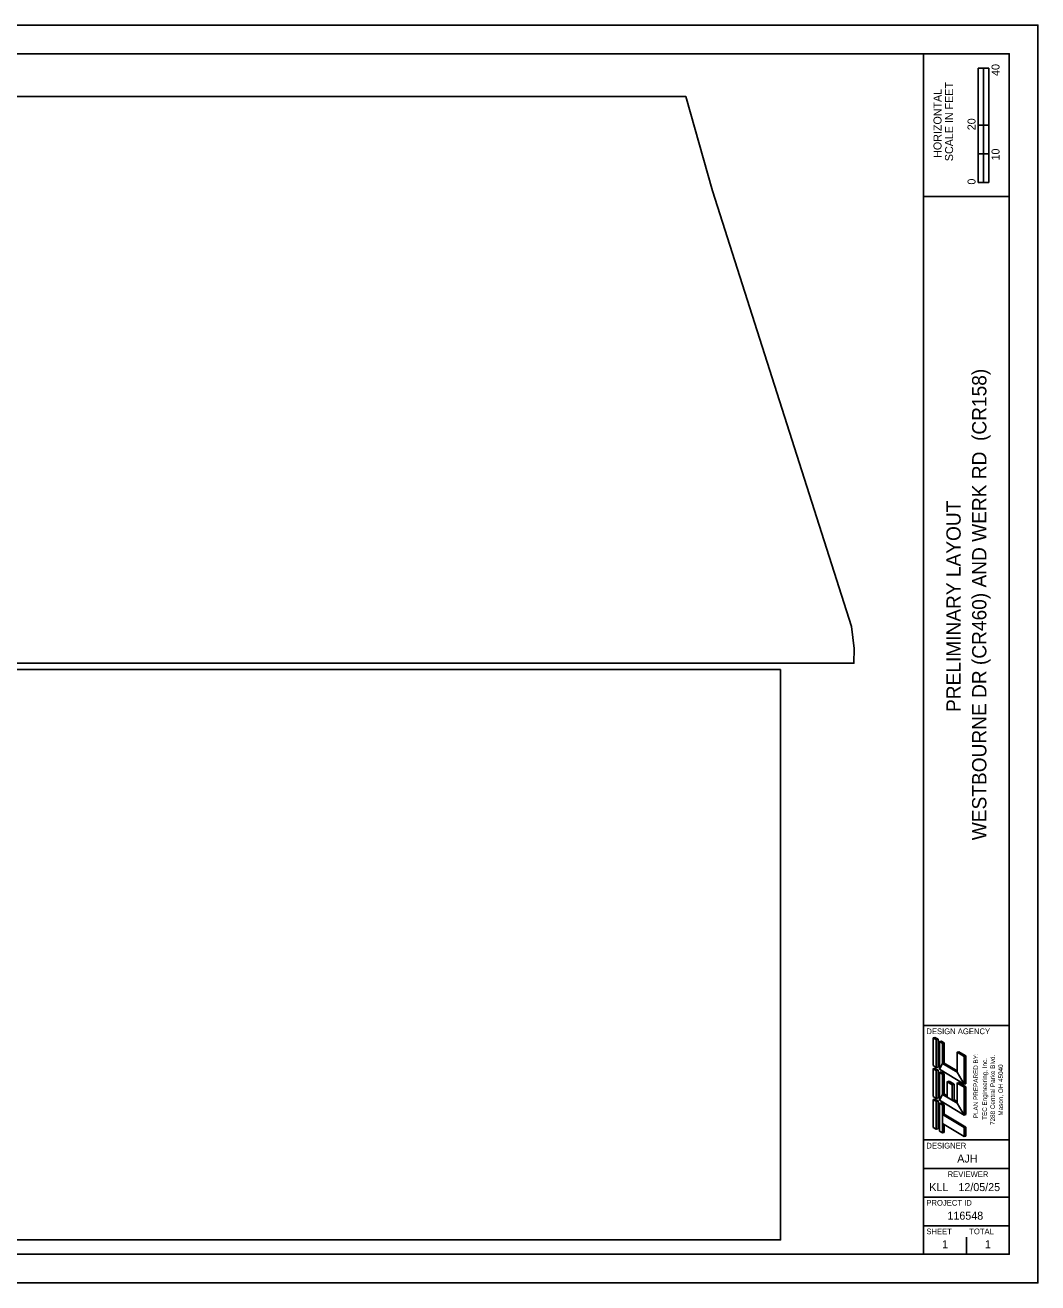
# Model space of a CAD drawing. Extents: x -1.4 to 34, y 0 to 22.
# Drawn here: x 16.29 to 34, y 0 to 22 of the extents above; entities that cross this region are included whole.
import ezdxf

# ---------------------------------------------------------------- set-up
doc = ezdxf.new("R2010")
doc.units = 0
for name, color, linetype in [('Default', 7, 'Continuous'), ('SC_Scratch1', 7, 'Continuous'), ('SH_Border', 7, 'Continuous'), ('SH_Cut_Line', 7, 'Continuous'), ('SH_Data', 7, 'Continuous'), ('SH_Text', 7, 'Continuous')]:
    doc.layers.add(name, color=color, linetype=linetype)

msp = doc.modelspace()

# ---------------------------------------------------------------- linework, layer by layer
at = {"layer": 'SC_Scratch1'}
for points in [[(27.845, 20.75), (4.5, 20.75), (4.5, 10.838), (30.783, 10.838), (30.786, 11.094), (30.743, 11.482), (28.307, 19.103)], [(27.845, 20.75), (7.965, 20.75), (7.965, 20.005), (4.5, 20.004), (4.5, 10.838), (30.783, 10.838), (30.786, 11.094), (30.743, 11.482), (28.307, 19.103)], [(29.5, 10.727), (4.5, 10.727), (4.5, 0.75), (29.5, 0.75)], [(29.5, 10.727), (4.5, 10.727), (4.5, 0.75), (29.5, 0.75)]]:
    msp.add_lwpolyline(points, close=True, dxfattribs=at)
at = {"layer": 'SH_Border'}
for p, q in [((32, 0.5), (32, 21.5)), ((32, 19), (33.5, 19)), ((32, 4.5), (33.5, 4.5)), ((32, 2.5), (33.5, 2.5)), ((32, 2), (33.5, 2)), ((32, 1.5), (33.5, 1.5)), ((32, 1), (33.5, 1))]:
    msp.add_line(p, q, dxfattribs=at)
msp.add_lwpolyline([(1.5, 21.5), (33.5, 21.5), (33.5, 0.5), (1.5, 0.5)], close=True, dxfattribs=at)
at = {"layer": 'SH_Cut_Line'}
msp.add_lwpolyline([(0, 0), (34, 0), (34, 22), (0, 22)], close=True, dxfattribs=at)
at = {"layer": 'SH_Data'}
for p, q in [((32.957, 19.25), (32.957, 21.25)), ((33.144, 21.25), (32.957, 21.25)), ((32.957, 20.25), (32.957, 21.25)), ((32.957, 21.25), (33.05, 21.25)), ((33.05, 21.25), (33.051, 21.25)), ((33.051, 21.25), (33.051, 20.25)), ((33.144, 21.25), (33.144, 19.25)), ((33.051, 20.25), (32.957, 20.25)), ((33.143, 20.25), (33.05, 20.25)), ((33.05, 20.25), (33.05, 19.75)), ((33.143, 19.75), (33.143, 20.25)), ((33.05, 19.75), (32.957, 19.75)), ((32.957, 19.75), (32.957, 19.25)), ((33.05, 19.25), (33.05, 19.75)), ((33.05, 19.75), (33.143, 19.75)), ((33.144, 19.25), (32.957, 19.25)), ((32.957, 19.25), (33.05, 19.25)), ((32.75, 3.5), (32.75, 3.5)), ((32.375, 0.675), (32.375, 0.675)), ((32.75, 0.5), (32.75, 0.8))]:
    msp.add_line(p, q, dxfattribs=at)
at = {"layer": 'SH_Text'}
for p, q in [((32.169, 4.285), (32.201, 4.294)), ((32.169, 3.799), (32.169, 4.285)), ((32.223, 4.253), (32.169, 4.285)), ((32.255, 4.261), (32.201, 4.294)), ((32.223, 4.253), (32.255, 4.261)), ((32.223, 3.767), (32.223, 4.253)), ((32.255, 3.775), (32.255, 4.261)), ((32.277, 4.221), (32.309, 4.229)), ((32.331, 4.188), (32.277, 4.221)), ((32.277, 3.735), (32.277, 4.221)), ((32.309, 4.229), (32.363, 4.196)), ((32.331, 4.188), (32.363, 4.196)), ((32.331, 3.837), (32.331, 4.188)), ((32.363, 4.196), (32.363, 3.845)), ((32.587, 4.034), (32.62, 4.042)), ((32.587, 3.683), (32.587, 4.034)), ((32.709, 3.961), (32.587, 4.034)), ((32.62, 4.042), (32.741, 3.97)), ((32.709, 3.961), (32.741, 3.97)), ((32.709, 3.475), (32.709, 3.961)), ((32.741, 3.97), (32.741, 3.484)), ((32.223, 3.767), (32.169, 3.799)), ((32.169, 3.745), (32.201, 3.754)), ((32.169, 3.259), (32.169, 3.745)), ((32.223, 3.713), (32.169, 3.745)), ((32.255, 3.722), (32.201, 3.754)), ((32.223, 3.767), (32.255, 3.775)), ((32.331, 3.837), (32.363, 3.845)), ((32.587, 3.683), (32.331, 3.837)), ((32.363, 3.845), (32.587, 3.711)), ((32.223, 3.713), (32.255, 3.722)), ((32.223, 3.227), (32.223, 3.713)), ((32.255, 3.236), (32.255, 3.722)), ((32.709, 3.475), (32.277, 3.735)), ((32.277, 3.681), (32.309, 3.689)), ((32.277, 3.195), (32.277, 3.681)), ((32.331, 3.648), (32.277, 3.681)), ((32.309, 3.689), (32.363, 3.656)), ((32.331, 3.648), (32.363, 3.656)), ((32.331, 3.297), (32.331, 3.648)), ((32.363, 3.656), (32.363, 3.305)), ((32.415, 3.519), (32.448, 3.527)), ((32.448, 3.527), (32.535, 3.474)), ((32.331, 3.297), (32.363, 3.305)), ((32.363, 3.305), (32.415, 3.274)), ((32.415, 3.519), (32.415, 3.247)), ((32.415, 3.519), (32.503, 3.466)), ((32.503, 3.466), (32.535, 3.474)), ((32.503, 3.466), (32.503, 3.194)), ((32.535, 3.474), (32.535, 3.202)), ((32.587, 3.494), (32.62, 3.502)), ((32.587, 3.143), (32.587, 3.494)), ((32.709, 3.421), (32.587, 3.494)), ((32.62, 3.502), (32.741, 3.43)), ((32.709, 3.475), (32.741, 3.484)), ((32.709, 3.421), (32.741, 3.43)), ((32.709, 2.935), (32.709, 3.421)), ((32.741, 3.43), (32.741, 2.944)), ((32.223, 3.227), (32.169, 3.259)), ((32.169, 3.205), (32.201, 3.215)), ((32.169, 2.719), (32.169, 3.205)), ((32.223, 3.173), (32.169, 3.205)), ((32.255, 3.181), (32.201, 3.215)), ((32.222, 3.173), (32.255, 3.181)), ((32.223, 3.227), (32.255, 3.236)), ((32.223, 2.687), (32.223, 3.173)), ((32.255, 2.695), (32.255, 3.181)), ((32.709, 2.935), (32.277, 3.195)), ((32.277, 3.141), (32.309, 3.151)), ((32.331, 3.108), (32.277, 3.141)), ((32.277, 2.655), (32.277, 3.141)), ((32.309, 3.151), (32.363, 3.116)), ((32.415, 3.247), (32.331, 3.297)), ((32.331, 3.108), (32.363, 3.116)), ((32.331, 2.944), (32.331, 3.108)), ((32.363, 3.116), (32.363, 2.952)), ((32.503, 3.194), (32.535, 3.202)), ((32.587, 3.143), (32.503, 3.194)), ((32.535, 3.202), (32.587, 3.171)), ((32.331, 2.944), (32.363, 2.952)), ((32.331, 2.944), (32.709, 2.717)), ((32.363, 2.952), (32.741, 2.725)), ((32.709, 2.935), (32.741, 2.944)), ((32.223, 2.687), (32.169, 2.719)), ((32.223, 2.687), (32.255, 2.695)), ((32.331, 2.622), (32.277, 2.655)), ((32.331, 2.787), (32.709, 2.56)), ((32.331, 2.622), (32.331, 2.787)), ((32.363, 2.63), (32.363, 2.767)), ((32.709, 2.717), (32.741, 2.725)), ((32.709, 2.56), (32.709, 2.717)), ((32.741, 2.725), (32.741, 2.568)), ((32.331, 2.622), (32.363, 2.63)), ((32.709, 2.56), (32.741, 2.568))]:
    msp.add_line(p, q, dxfattribs=at)
for points in [[(32.169, 3.799), (32.223, 3.767), (32.223, 4.253), (32.169, 4.285)], [(32.277, 3.735), (32.331, 3.837), (32.331, 4.188), (32.277, 4.221)], [(32.709, 3.475), (32.587, 3.683), (32.587, 4.034), (32.709, 3.961)], [(32.169, 3.259), (32.223, 3.227), (32.223, 3.713), (32.169, 3.745)], [(32.277, 3.735), (32.331, 3.837), (32.587, 3.683), (32.709, 3.475)], [(32.277, 3.195), (32.331, 3.297), (32.331, 3.648), (32.277, 3.681)], [(32.415, 3.247), (32.415, 3.519), (32.503, 3.466), (32.503, 3.194)], [(32.709, 2.935), (32.587, 3.143), (32.587, 3.494), (32.709, 3.421)], [(32.169, 2.719), (32.223, 2.687), (32.223, 3.173), (32.169, 3.205)], [(32.277, 3.195), (32.331, 3.297), (32.587, 3.143), (32.709, 2.935)], [(32.277, 2.655), (32.331, 2.622), (32.331, 3.108), (32.277, 3.141)], [(32.331, 2.787), (32.331, 2.944), (32.709, 2.717), (32.709, 2.56)]]:
    msp.add_lwpolyline(points, close=True, dxfattribs=at)

# ---------------------------------------------------------------- texts
at = {"layer": 'Default'}
for s, p in [('PLAN PREPARED BY:', (32.954, 2.88)), ('TEC Engineering, Inc.', (33.11, 2.851)), ('7288 Central Parke Blvd.', (33.25, 2.762)), ('Mason, OH 45040', (33.39, 2.925))]:
    msp.add_text(s, height=0.08, rotation=90, dxfattribs=at).set_placement(p)
at = {"layer": 'SH_Data'}
for s, height, p in [('40', 0.14, (33.33, 21.112)), ('SCALE IN FEET', 0.14, (32.517, 19.621)), ('HORIZONTAL', 0.14, (32.315, 19.679)), ('20', 0.14, (32.91, 20.162)), ('10', 0.14, (33.33, 19.633)), ('0', 0.14, (32.91, 19.211)), ('WESTBOURNE DR (CR460) AND WERK RD  (CR158)', 0.25, (33.1, 7.742)), ('PRELIMINARY LAYOUT', 0.25, (32.65, 9.986))]:
    msp.add_text(s, height=height, rotation=90, dxfattribs=at).set_placement(p)
for s, height, p in [('DESIGN AGENCY', 0.1, (32.05, 4.35)), ('DESIGNER', 0.1, (32.05, 2.35)), ('AJH', 0.14, (32.59, 2.105)), ('REVIEWER', 0.1, (32.422, 1.85)), ('KLL', 0.14, (32.101, 1.605)), ('12/05/25', 0.14, (32.611, 1.605)), ('PROJECT ID', 0.1, (32.05, 1.35)), ('116548', 0.14, (32.419, 1.105)), ('SHEET', 0.1, (32.05, 0.85)), ('TOTAL', 0.1, (32.8, 0.85)), ('1', 0.14, (32.325, 0.605)), ('1', 0.14, (33.075, 0.605))]:
    msp.add_text(s, height=height, dxfattribs=at).set_placement(p)

doc.saveas('drawing.dxf')
